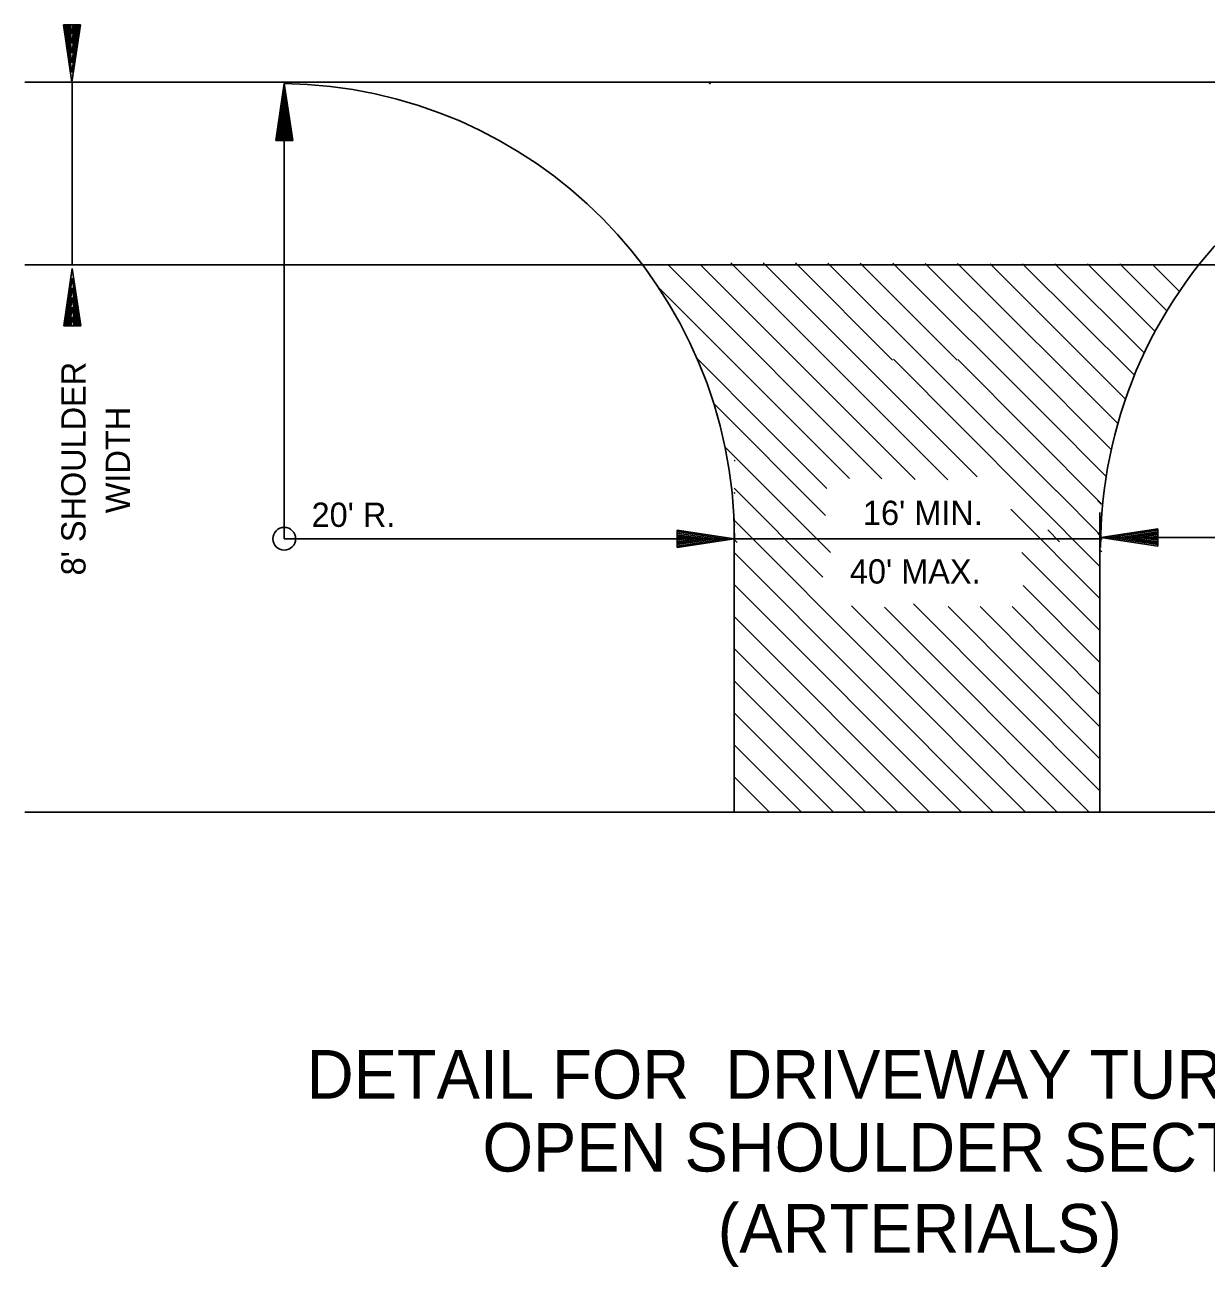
# Model space of a CAD drawing. Extents: x 1227242 to 1227801, y 152460 to 152569.
# Drawn here: x 1227362.71 to 1227368.79, y 152470.71 to 152477.11 of the extents above; entities that cross this region are included whole.
import ezdxf

# ---------------------------------------------------------------- set-up
doc = ezdxf.new("R2010")
doc.units = 0
doc.layers.add('Default', color=7, linetype='Continuous')

msp = doc.modelspace()

# ---------------------------------------------------------------- linework, layer by layer
at = {"layer": 'Default'}
for p, q in [((1227362.9059, 152477.1103), (1227362.9501, 152476.8155)), ((1227362.9945, 152477.1103), (1227362.9059, 152477.1103)), ((1227362.9128, 152477.1103), (1227362.9501, 152476.8646)), ((1227362.9211, 152477.1103), (1227362.9501, 152476.9152)), ((1227362.9286, 152477.1103), (1227362.9501, 152476.9644)), ((1227362.9357, 152477.1103), (1227362.9501, 152477.0145)), ((1227362.9432, 152477.1103), (1227362.9501, 152477.0626)), ((1227362.9945, 152477.1103), (1227362.9501, 152476.8155)), ((1227362.9639, 152477.1103), (1227362.9501, 152477.0145)), ((1227362.98, 152477.1103), (1227362.9501, 152476.9152)), ((1227362.9874, 152477.1103), (1227362.9501, 152476.8646)), ((1227362.9718, 152477.1103), (1227362.9501, 152476.9644)), ((1227362.9572, 152477.1103), (1227362.9501, 152477.0626)), ((1227362.7076, 152476.8155), (1227371.9168, 152476.8155)), ((1227362.9514, 152475.8742), (1227362.9514, 152476.8155)), ((1227363.9991, 152476.5139), (1227364.0433, 152476.8081)), ((1227364.087, 152476.5139), (1227364.0433, 152476.8081)), ((1227364.0433, 152474.4637), (1227364.0433, 152476.8081)), ((1227366.2331, 152476.8057), (1227366.2372, 152476.8186)), ((1227366.2372, 152476.8144), (1227366.2331, 152476.8057)), ((1227366.2331, 152476.8057), (1227366.2372, 152476.8099)), ((1227364.006, 152476.5139), (1227364.0433, 152476.7585)), ((1227364.0799, 152476.5139), (1227364.0433, 152476.7585)), ((1227364.0135, 152476.5139), (1227364.0433, 152476.7079)), ((1227364.0725, 152476.5139), (1227364.0433, 152476.7079)), ((1227364.0209, 152476.5139), (1227364.0433, 152476.6594)), ((1227364.0292, 152476.5139), (1227364.0433, 152476.6092)), ((1227364.0646, 152476.5139), (1227364.0433, 152476.6594)), ((1227364.0576, 152476.5139), (1227364.0433, 152476.6092)), ((1227364.036, 152476.5139), (1227364.0433, 152476.5602)), ((1227364.0504, 152476.5139), (1227364.0433, 152476.5602)), ((1227363.9991, 152476.5139), (1227364.087, 152476.5139)), ((1227362.7076, 152475.8742), (1227371.9168, 152475.8742)), ((1227362.908, 152475.5608), (1227362.9519, 152475.8555)), ((1227362.9963, 152475.5608), (1227362.9519, 152475.8555)), ((1227362.9153, 152475.5608), (1227362.9519, 152475.8052)), ((1227362.9887, 152475.5608), (1227362.9519, 152475.8052)), ((1227362.9229, 152475.5608), (1227362.9519, 152475.7552)), ((1227362.9818, 152475.5608), (1227362.9519, 152475.7552)), ((1227362.9298, 152475.5608), (1227362.9519, 152475.7063)), ((1227362.9378, 152475.5608), (1227362.9519, 152475.656)), ((1227362.9733, 152475.5608), (1227362.9519, 152475.7063)), ((1227362.9664, 152475.5608), (1227362.9519, 152475.656)), ((1227362.9451, 152475.5608), (1227362.9519, 152475.6072)), ((1227362.959, 152475.5608), (1227362.9519, 152475.6072)), ((1227362.908, 152475.5608), (1227362.9963, 152475.5608)), ((1227367.1799, 152475.3879), (1227368.2433, 152474.3212)), ((1227367.5109, 152475.3861), (1227368.257, 152474.6378)), ((1227366.2542, 152475.1603), (1227366.8294, 152474.5832)), ((1227367.9693, 152475.0913), (1227368.2752, 152474.7846)), ((1227366.5197, 152475.0404), (1227366.8368, 152474.7224)), ((1227366.3124, 152474.9369), (1227366.8549, 152474.3928)), ((1227366.3603, 152474.7238), (1227366.8169, 152474.2655)), ((1227368.0182, 152474.712), (1227368.2433, 152474.4862)), ((1227366.3603, 152474.5675), (1227366.3603, 152474.4575)), ((1227366.3603, 152474.5588), (1227367.859, 152473.0554)), ((1227367.7844, 152474.6163), (1227368.2433, 152474.1561)), ((1227368.2433, 152474.5993), (1227368.2433, 152474.4649)), ((1227366.0661, 152474.5074), (1227366.3603, 152474.4637)), ((1227366.0661, 152474.5074), (1227366.0661, 152474.4191)), ((1227366.0661, 152474.5006), (1227366.3106, 152474.4637)), ((1227366.0661, 152474.4929), (1227366.2604, 152474.4637)), ((1227368.5411, 152474.5143), (1227368.2472, 152474.4701)), ((1227368.5411, 152474.5074), (1227368.2964, 152474.4701)), ((1227368.5411, 152474.4999), (1227368.3471, 152474.4701)), ((1227368.5411, 152474.4923), (1227368.3956, 152474.4701)), ((1227368.5411, 152474.4265), (1227368.5411, 152474.5143)), ((1227366.3603, 152474.4637), (1227364.0433, 152474.4637)), ((1227366.0661, 152474.4844), (1227366.2112, 152474.4637)), ((1227366.0661, 152474.4779), (1227366.1613, 152474.4637)), ((1227366.0661, 152474.4705), (1227366.1122, 152474.4637)), ((1227366.0661, 152474.4191), (1227366.3603, 152474.4637)), ((1227366.0661, 152474.4488), (1227366.1613, 152474.4637)), ((1227366.0661, 152474.434), (1227366.2604, 152474.4637)), ((1227366.0661, 152474.426), (1227366.3106, 152474.4637)), ((1227366.0661, 152474.4414), (1227366.2112, 152474.4637)), ((1227366.0661, 152474.4564), (1227366.1122, 152474.4637)), ((1227366.3603, 152474.4637), (1227366.3603, 152473.0554)), ((1227366.3603, 152474.4637), (1227368.0203, 152474.4637)), ((1227367.974, 152474.4637), (1227368.2538, 152474.4637)), ((1227368.2433, 152473.0529), (1227368.2433, 152474.4701)), ((1227368.5411, 152474.4265), (1227368.2472, 152474.4701)), ((1227368.2472, 152474.4701), (1227370.6276, 152474.4701)), ((1227368.5411, 152474.4334), (1227368.2964, 152474.4701)), ((1227368.5411, 152474.4409), (1227368.3471, 152474.4701)), ((1227368.5411, 152474.4488), (1227368.3956, 152474.4701)), ((1227368.5411, 152474.4854), (1227368.4456, 152474.4701)), ((1227368.5411, 152474.4562), (1227368.4456, 152474.4701)), ((1227368.5411, 152474.477), (1227368.4945, 152474.4701)), ((1227368.5411, 152474.463), (1227368.4945, 152474.4701)), ((1227366.3603, 152474.3936), (1227367.6941, 152473.0554)), ((1227367.8416, 152474.3936), (1227368.2433, 152473.9911)), ((1227366.3603, 152474.2282), (1227367.5294, 152473.0554)), ((1227367.8479, 152474.2224), (1227368.2433, 152473.8258)), ((1227366.9631, 152474.1188), (1227368.0233, 152473.0554)), ((1227367.1345, 152474.1123), (1227368.1882, 152473.0554)), ((1227367.2837, 152474.128), (1227368.2433, 152473.1654)), ((1227367.461, 152474.1148), (1227368.2433, 152473.3303)), ((1227367.626, 152474.1144), (1227368.2433, 152473.4957)), ((1227367.7912, 152474.1142), (1227368.2433, 152473.6608)), ((1227366.3603, 152474.0632), (1227367.3648, 152473.0554)), ((1227366.3603, 152473.8979), (1227367.2, 152473.0554)), ((1227366.3603, 152473.7325), (1227367.0357, 152473.0554)), ((1227366.3603, 152473.5675), (1227366.8711, 152473.0554)), ((1227366.3603, 152473.4024), (1227366.7062, 152473.0554)), ((1227366.3603, 152473.2374), (1227366.5419, 152473.0554)), ((1227362.7076, 152473.0554), (1227371.9168, 152473.0554))]:
    msp.add_line(p, q, dxfattribs=at)
for points in [[(1227366.0204, 152475.8742), (1227367.1208, 152474.773)], [(1227366.1864, 152475.8742), (1227367.292, 152474.7696)], [(1227366.3418, 152475.8852), (1227367.4591, 152474.768)], [(1227366.5083, 152475.8846), (1227367.6108, 152474.7829)], [(1227366.6756, 152475.884), (1227367.1755, 152475.3836)], [(1227366.8422, 152475.8828), (1227368.017, 152474.7108)], [(1227367.0089, 152475.8828), (1227367.5084, 152475.3836)], [(1227367.1775, 152475.8823), (1227367.9693, 152475.0913)], [(1227367.3434, 152475.8817), (1227367.8428, 152475.3836)], [(1227367.5104, 152475.8811), (1227368.3349, 152475.0571)], [(1227367.6776, 152475.8799), (1227368.3747, 152475.1834)], [(1227367.8441, 152475.8799), (1227368.4205, 152475.3057)], [(1227368.0113, 152475.8799), (1227368.471, 152475.4209)], [(1227368.1786, 152475.8792), (1227368.5269, 152475.5309)], [(1227368.3458, 152475.879), (1227368.5874, 152475.6373)], [(1227368.5157, 152475.8742), (1227368.6521, 152475.7378)], [(1227365.9704, 152475.7577), (1227366.9532, 152474.7739)], [(1227366.1676, 152475.394), (1227366.5197, 152475.0404)], [(1227367.8424, 152475.3836), (1227368.3013, 152474.9232)], [(1227366.3603, 152474.8685), (1227366.3649, 152474.8638)], [(1227368.2305, 152474.8293), (1227368.2433, 152474.8165)], [(1227366.3603, 152474.7021), (1227366.3637, 152474.6971)], [(1227368.231, 152474.6608), (1227368.2501, 152474.6421)], [(1227366.3591, 152474.5367), (1227366.363, 152474.5321)], [(1227367.974, 152474.5097), (1227368.0345, 152474.4484)], [(1227368.2314, 152474.4941), (1227368.2433, 152474.4829)], [(1227366.363, 152474.4558), (1227366.3749, 152474.4438)], [(1227368.2389, 152474.4104), (1227368.2528, 152474.3971)]]:
    msp.add_lwpolyline(points, dxfattribs=at)
msp.add_circle((1227364.0431, 152474.4636), 0.0588, dxfattribs=at)
for centre, radius, start, end in [((1227364.0135, 152474.4606), 2.3475, 0.07639, 89.27429), ((1227370.595, 152474.4191), 2.3484, 88.75379, 180)]:
    msp.add_arc(centre, radius, start, end, dxfattribs=at)

# ---------------------------------------------------------------- texts
for s, p in [("8' SHOULDER", (1227363.02, 152474.2751)), ('WIDTH', (1227363.2487, 152474.5954))]:
    msp.add_text(s, height=0.125, rotation=90, dxfattribs=at).set_placement(p)
for s, height, p in [("20' R.", 0.125, (1227364.1837, 152474.525)), ("16' MIN.", 0.125, (1227367.0228, 152474.5348)), ("40' MAX.", 0.125, (1227366.9554, 152474.2331)), ('DETAIL FOR  DRIVEWAY TURNOUTS', 0.25, (1227364.1592, 152471.5807)), ('OPEN SHOULDER SECTION', 0.25, (1227365.0638, 152471.2052)), ('(ARTERIALS)', 0.25, (1227366.275, 152470.788))]:
    msp.add_text(s, height=height, dxfattribs=at).set_placement(p)

doc.saveas('drawing.dxf')
